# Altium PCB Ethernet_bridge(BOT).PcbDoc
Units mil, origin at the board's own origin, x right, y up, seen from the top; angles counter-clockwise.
Board outline 3110.24 x 1181.1 mil, 2 copper layers (Top Layer, Bottom Layer), stack 35.4 mil thick; 47 components, 34 nets, 155 pads, 0 vias.
Unrouted connection lines stored in the file: 106.
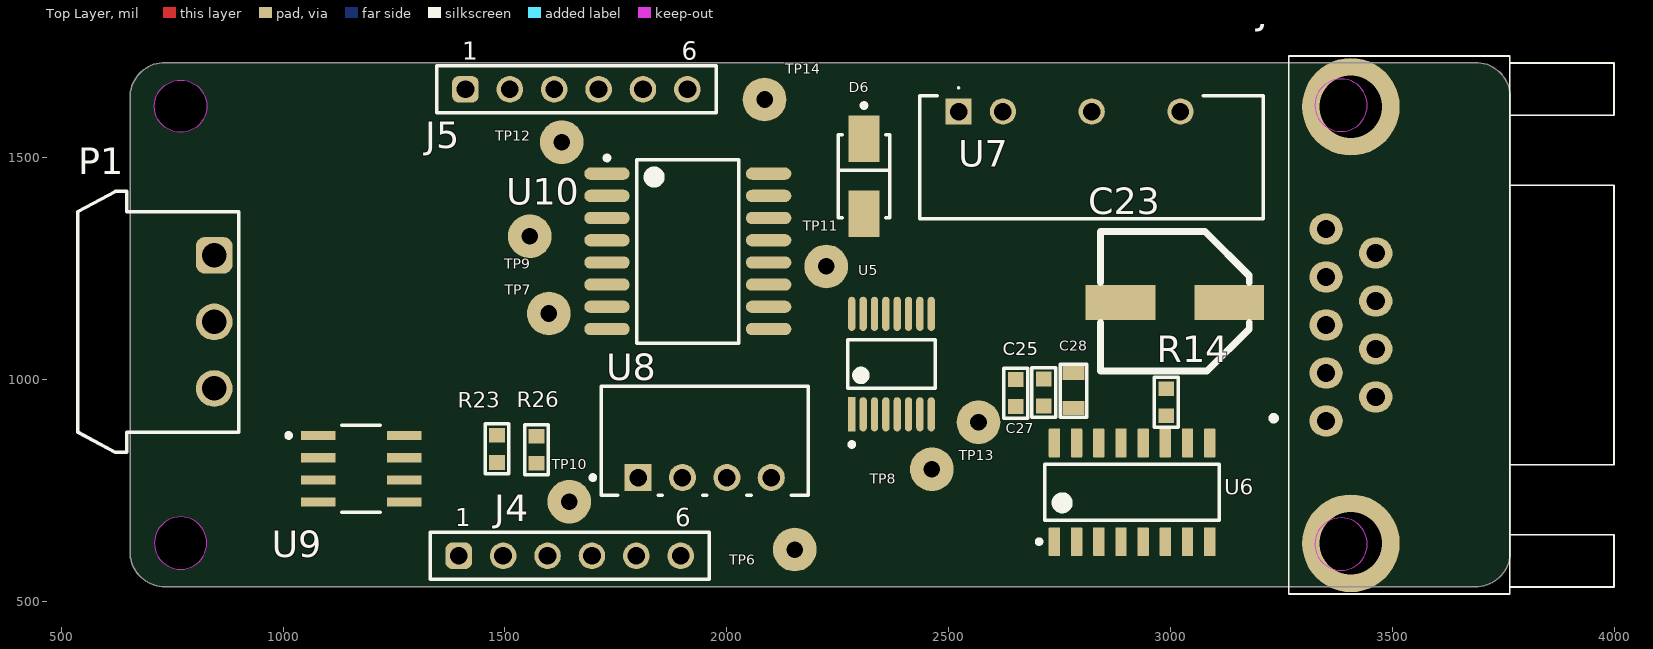
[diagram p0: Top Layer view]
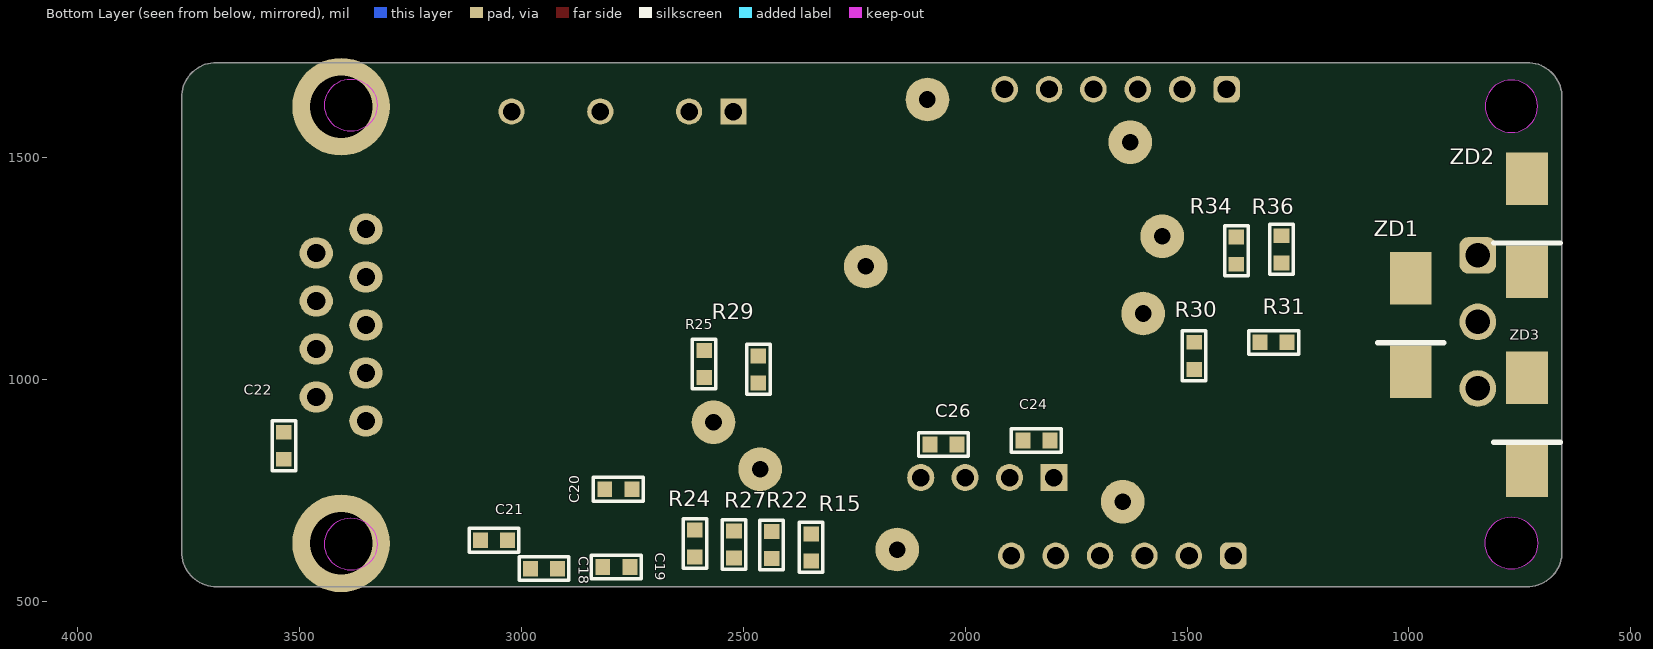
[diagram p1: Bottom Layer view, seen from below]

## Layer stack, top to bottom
Top Solder: solder mask 0.4, Solder Resist, Dk 3.5
Top Layer: signal copper 1.4
Dielectric 1: dielectric 32.6, FR-4, Dk 4.8
Bottom Layer: signal copper 1.4
Bottom Solder: solder mask 0.4, Solder Resist, Dk 3.5

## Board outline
733.99,532.25 cw(c733.99,610.99) 655.25,610.99 655.25,1634.61 cw(c733.99,1634.61) 733.99,1713.35 3686.75,1713.35 cw(c3686.75,1634.61) 3765.49,1634.61 3765.49,610.99 cw(c3686.75,610.99) 3686.75,532.25
cut-out: 3324.94,628.39 ccw(c3383.99,628.39) 3383.99,569.34 ccw(c3383.99,628.39) 3443.05,628.39 ccw(c3383.99,628.39) 3383.99,687.45 ccw(c3383.99,628.39)
cut-out: 3324.94,1617.21 ccw(c3383.99,1617.21) 3383.99,1558.16 ccw(c3383.99,1617.21) 3443.05,1617.21 ccw(c3383.99,1617.21) 3383.99,1676.27 ccw(c3383.99,1617.21)
cut-out: 769.42,1555.87 cw(c769.42,1614.93) 710.37,1614.93 cw(c769.42,1614.93) 769.42,1673.98 cw(c769.42,1614.93) 828.48,1614.93 cw(c769.42,1614.93)
cut-out: 710.37,630.68 ccw(c769.42,630.68) 769.42,571.62 ccw(c769.42,630.68) 828.48,630.68 ccw(c769.42,630.68) 769.42,689.73 ccw(c769.42,630.68)

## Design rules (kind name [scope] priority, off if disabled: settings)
Clearance [All] p1: gap=1 ignorepadtopadclearanceinfootprint=TRUE
ComponentClearance ComponentClearance_1 [All] p1: gap=-100 collisioncheckmode=3 verticalgap=100000 showdistances=FALSE
PolygonConnect [All] p1: connectstyle=Relief reliefconductorwidth=10 reliefentries=4 polygonreliefangle="90 Angle" airgapwidth=10
RoutingVias [All] p1: holewidth=28 width=50 viastyle="Through Hole" minholewidth=28 minwidth=50 maxholewidth=28 maxwidth=50
ShortCircuit [All] p1: allowed=TRUE
SolderMaskExpansion [All] p1: expansion=4 istentingtop=FALSE
SupplyNets "Schematic Supply Nets_6" [InNet('GND')] p1: voltage=0.000
SupplyNets "Schematic Supply Nets_5" [InNet('+5V')] p2: voltage=0.000
SupplyNets "Schematic Supply Nets_4" [InNet('VCC')] p3: voltage=0.000
SupplyNets "Schematic Supply Nets_3" [InNet('GND_2')] p4: voltage=0.000
SupplyNets "Schematic Supply Nets_2" [InNet('+3V3_MCU')] p5: voltage=0.000
SupplyNets "Schematic Supply Nets" [InNet('+5V_ISO')] p6: voltage=0.000
Width [All] p1: maxlimit=10 minlimit=10 preferedwidth=10
28 further rules are at their usual default settings.

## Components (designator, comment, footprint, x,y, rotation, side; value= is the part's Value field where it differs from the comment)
C18 "0.1uF" CAP-0603 2949,573 r180 bottom
C19 "0.1uF" CAP-0603 2786,577 r180 bottom
C20 "0.1uF" CAP-0603 2781.49,752 r0 bottom
C21 "0.1uF" CAP-0603 3061.51,637 r180 bottom
C22 "100nF" CAP-0603 3535,850 r90 bottom
C23 "330uF 25V" CAP_SMD_Size_E 3007,1173 r0 top
C24 "100nF" CAP-0603 1839.49,862 r0 bottom
C25 "100nF" CAP-0603 2651,968.51 r90 top
C26 "100nF" CAP-0603 2049,853 r0 bottom
C27 "100nF" CAP-0603 2714,970 r90 top
C28 "0.47uF" CAP-0805 2781,974 r90 top
D6 "SS14" DO-214-AC 2309,1457 r90 top
J1 "DB9 pcb" DB-9_2 2365.19,1476.98 r90 top
J4 "61300611821" 61300611821 1646,602 r0 top
J5 "61300611821" 61300611821 1661,1653 r0 top
P1 "691305340003" 691305340003 719,1129 r270 top
R14 "33R" RES-0603 2990,948 r90 top
R15 "33R" RES-0603 2347,621 r90 bottom
R22 "10K" RES-0603 2436,626.51 r90 bottom
R23 "10K" RES-0603 1482,843 r90 top
R24 "10K" RES-0603 2609,629.51 r90 bottom
R25 "10K" RES-0603 2588,1034 r90 bottom
R26 "10K" RES-0603 1571,841 r90 top
R27 "100" RES-0603 2521,627.51 r90 bottom
R29 "100" RES-0603 2466,1022 r90 bottom
R30 "10K" RES-0603 1484,1052.51 r90 bottom
R31 "10K" RES-0603 1305,1083 r180 bottom
R34 "10K" RES-0603 1389,1289.51 r90 bottom
R36 "10K" RES-0603 1287,1292.51 r90 bottom
TP6 "Test_Point_PCB" Test_Point 2153,616 r0 top
TP7 "Test_Point_PCB" Test_Point 1599,1148 r0 top
TP8 "Test_Point_PCB" Test_Point 2462,797 r0 top
TP9 "Test_Point_PCB" Test_Point 1556,1322 r0 top
TP10 "Test_Point_PCB" Test_Point 1645,724 r90 top
TP11 "Test_Point_PCB" Test_Point 2224,1254 r90 top
TP12 "Test_Point_PCB" Test_Point 1628,1534 r90 top
TP13 "" Test_Point 2567,903 r90 top
TP14 "Test_Point_PCB" Test_Point 2085,1630 r90 top
U5 "TMUX1574PWR" TSSOP-16-A 2371,1034 r90 top
U6 "MAX3232" SOIC-16-M 2913,745 r90 top
U7 "B1212S-3WR2" B1212S-3WR2 2822,1508 r0 top
U8 "B0505S-1W" B0505S-1W 1950,861 r0 top
U9 "MAX485" SOIC-8-MFG 1176,798 r0 top
U10 "ADUM1401BRWZ" ADI-RW-16_M 1912,1288 r0 top
ZD1 "P6SMB16CA" DO-214AA 996,1032 r90 bottom
ZD2 "P6SMB16CA" DO-214AA 734,1257 r90 bottom
ZD3 "P6SMB16CA" DO-214AA 734,808 r90 bottom

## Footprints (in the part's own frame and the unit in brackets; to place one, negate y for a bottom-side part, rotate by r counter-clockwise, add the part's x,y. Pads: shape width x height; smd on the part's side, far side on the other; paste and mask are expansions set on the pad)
61300611821 [mm] "Socket Header, Pitch 2.54 mm, THT, Vertical, single row, 6p"
  rrect50% 1.52x1.52 hole 1.02: 1(-6.35,0)
  round 1.52 hole 1.02: 2(-3.81,0) 3(-1.27,0) 4(1.27,0) 5(3.81,0) 6(6.35,0)
  silkscreen extent -8,-1.35 8,1.35, body extent -7.87,-1.25 7.87,1.25, height 8.55
691305340003 [mm] "Horizontal PCB Header with Plastic Latch, pitch 3.81mm, 03p"
  rrect50% 2.1x2.1 hole 1.4: 1(-3.81,3.2)
  round 2.1 hole 1.4: 2(0,3.2) 3(3.81,3.2)
  silkscreen extent -7.47,-4.6 7.47,4.6, body extent -7.46,-4.6 7.46,4.6, height 7.25
ADI-RW-16_M [mm] "SOIC, 16-Leads, Body 10.3x7.5mm, Pitch 1.27mm, IPC Low Density"
  oval 2.6x0.7 smd: 1(-4.625,4.445) 2(-4.625,3.175) 3(-4.625,1.905) 4(-4.625,0.635) 5(-4.625,-0.635) 6(-4.625,-1.905) 7(-4.625,-3.175) 8(-4.625,-4.445) 9(4.625,-4.445) 10(4.625,-3.175) 11(4.625,-1.905) 12(4.625,-0.635) 13(4.625,0.635) 14(4.625,1.905) 15(4.625,3.175) 16(4.625,4.445)
  silkscreen extent -4.75,-5.25 2.93,5.47, body extent -3.8,-5.25 3.8,5.25, height 2.65
B0505S-1W [mm]
  rect 1.55x1.55 hole 1 paste-2539.97 mask+0: 1(-3.81,-2.1)
  round 1.55 hole 1 paste-2539.97 mask+0: 2(-1.27,-2.1) 3(1.27,-2.1) 4(3.81,-2.1)
  silkscreen extent -6.52,-3.13 5.92,3.13, body extent -6.02,-3.22 6.02,3.22, height 0.25
B1212S-3WR2 [mm]
  rect 1.5x1.5 hole 1: 1(-7.62,2.413)
  round 1.5 hole 1: 2(-5.08,2.413) 4(0,2.413) 6(5.08,2.413)
  silkscreen extent -9.83,-3.74 9.82,3.81, body extent -9.8,-3.68 9.8,3.32, height 10
CAP-0603 [mm]
  rect 0.85x0.9 smd: 1(-0.775,0) 2(0.775,0)
  silkscreen extent -1.43,-0.67 1.43,0.67, body extent -0.8,-0.4 0.8,0.4, height 0.8
CAP-0805 [mm]
  rect 0.8x1.25 smd mask+0.015: 1(-1,0) 2(1,0)
  silkscreen extent -1.52,-0.76 1.52,0.76, body extent -1,-0.62 1,0.63, height 0.8
CAP_SMD_Size_E [mm]
  rect 4x2 smd: 1(3.175,0) 2(-3.048,0)
  silkscreen extent -4.19,-3.94 4.32,4.06, body extent -4.25,-4 4.25,4, height 10.59
DB-9_2 [mil]
  oval 70x75 hole 40.94: 1(-570.98,-985) 2(-462.99,-985) 3(-355,-985) 4(-246.97,-985) 5(-138.98,-985) 6(-516.97,-1096.81) 7(-408.98,-1096.81) 8(-300.98,-1096.81) 9(-192.99,-1096.81)
  round 220 hole 140.87: MH1(-846.93,-1040.91) MH2(136.93,-1040.91)
  silkscreen extent -961,-1634 251,-861, body extent -971,-1655 261,-915, height 494
DO-214-AC [mm]
  rect 2.65x1.75 smd paste+0 mask+0: 1(-2.15,0) 2(2.15,0)
  silkscreen extent -2.37,-1.48 4.17,1.48, body extent -3.57,-1.58 3.57,1.58, height 0.25
DO-214AA [mm]
  rect 3x2.4 smd: 1(-0.381,0) 2(4.953,0)
  silkscreen extent 1.27,-1.91 1.27,1.91, body extent -0.53,-1.85 5.07,2.1, height 2.65
RES-0603 [mm]
  rect 0.85x0.9 smd: 1(-0.775,0) 2(0.775,0)
  silkscreen extent -1.43,-0.67 1.43,0.67, body extent -0.85,-0.45 0.85,0.45, height 0.55
SOIC-8-MFG [mm]
  rect 1.98x0.53 smd paste+0 mask+0: 1(-2.465,1.905) 2(-2.465,0.635) 3(-2.465,-0.635) 4(-2.465,-1.905) 5(2.465,-1.905) 6(2.465,-0.635) 7(2.465,0.635) 8(2.465,1.905)
  silkscreen extent -4.27,-2.5 1.1,2.5, body extent -3.55,-2.75 3.55,2.75, height 0.25
SOIC-16-M [mm]
  rrect15% 1.65x0.65 smd: 1(-2.825,4.445) 2(-2.825,3.175) 3(-2.825,1.905) 4(-2.825,0.635) 5(-2.825,-0.635) 6(-2.825,-1.905) 7(-2.825,-3.175) 8(-2.825,-4.445) 9(2.825,-4.445) 10(2.825,-3.175) 11(2.825,-1.905) 12(2.825,-0.635) 13(2.825,0.635) 14(2.825,1.905) 15(2.825,3.175) 16(2.825,4.445)
  silkscreen extent -2.95,-5 1.6,5.44, body extent -3,-4.95 3,4.95, height 1.59
Test_Point [mm]
  round 2.5 hole 0.95: 1(0,0)
TSSOP-16-A [mm] "TSSOP-16 pacadge"
  rect 1.955x0.421 smd paste+0 mask+0: 1(-2.875,2.275)
  rrect100% 1.955x0.421 smd paste+0 mask+0: 2(-2.875,1.625) 3(-2.875,0.975) 4(-2.875,0.325) 5(-2.875,-0.325) 6(-2.875,-0.975) 7(-2.875,-1.625) 8(-2.875,-2.275) 9(2.875,-2.275) 10(2.875,-1.625) 11(2.875,-0.975) 12(2.875,-0.325) 13(2.875,0.325) 14(2.875,0.975) 15(2.875,1.625) 16(2.875,2.275)
  silkscreen extent -4.73,-2.5 1.4,2.5, body extent -4.35,-3 4.35,3, height 0.25

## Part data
C18 C19 C20 C21 C22 C24 C25 C26 C27 C28: library part CAP-NON-POLAR
C23: library part CAP_POL_SMD
J1: library part DB9
J4 J5: "WR-PHD Socket Header, THT, Vertical, pitch 2.54mm, 1 Row, 6P", Contact Resistance=20mΩ, Manufacturer="Wurth Elektronik", Operating Temperature Max=125°C, Operating Temperature Min=-40°C, Rated Current=3A, Withstanding Voltage=500V, Working Voltage=250V
P1: "WR-TBL Series 3053 Horizontal PCB Header, THT, pitch 3.81mm, 3p", Manufacturer="Wurth Elektronik", Operating Temperature Max=105°C, Operating Temperature Min=-40°C, Rated Current=12A, Working Voltage=300V
R14 R15 R22 R23 R24 R25 R26 R27 R29 R30 R31 R34 R36: library part RES-CONST
TP6 TP7 TP8 TP9 TP10 TP11 TP12 TP13 TP14: library part TP_PCB?, "Test_Point"
U10: library part CMP-0534-00565-1, "Quad Channel Digital Isolator, 2.5 KV rms Insulation Rating, 10 Mbps Data Rate, 50 ns Delay, Industrial, 16-pin SOIC (RW-16), Tube", Manufacturer="Analog Devices", Max Operating Temp (degreesC)=125

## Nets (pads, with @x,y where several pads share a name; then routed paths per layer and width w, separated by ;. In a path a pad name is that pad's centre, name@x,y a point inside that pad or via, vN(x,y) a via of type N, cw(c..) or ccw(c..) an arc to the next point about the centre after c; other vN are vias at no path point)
+3V3_MCU: J4.4 J5.1 R23.2 R26.2 U10.1 U10.7
+5V: C24.2 J4.3 U8.2
+5V_ISO: C25.2 C26.2 C27.2 C28.1 R22.2 R24.2 R25.2 TP6.1 U5.16 U6.16 U8.4 U9.8 U10.10 U10.16
GND: C24.1 J4.5 J4.6 J5.6 R30.1 R31.1 U7.4 U8.1 U10.2 U10.8
GND_2: C20.1 C21.1 C22.1 C23.2 C25.1 C26.1 C27.1 C28.2 J1.5 J1.MH1 J1.MH2 P1.2 R34.1 R36.1 TP14.1 U5.8 U5.15 U6.15 U7.2 U8.3 U9.5 U10.9 U10.15 ZD2.1 ZD3.1
NetC18_1: C18.1 U6.5
NetC18_2: C18.2 U6.4
NetC19_1: C19.1 U6.3
NetC19_2: C19.2 U6.1
NetC20_2: C20.2 U6.2
NetC21_2: C21.2 U6.6
NetC22_2: C22.2 C23.1 J1.9 U7.1
NetD6_1: D6.1 U7.6
NetJ1_2: J1.2 U6.13
NetJ1_3: J1.3 U6.14
NetJ5_2: J5.2 R31.2 TP9.1 U10.3
NetJ5_3: J5.3 R26.1 TP10.1 U10.4
NetJ5_4: J5.4 R23.1 TP12.1 U10.6
NetJ5_5: J5.5 R30.2 TP7.1 U10.5
NetP1_1: P1.1 R22.1 U9.6 ZD1.2 ZD2.2
NetP1_3: P1.3 R34.2 U9.7 ZD1.1 ZD3.2
NetR14_1: R14.1 U6.11
NetR14_2: R14.2 U5.2
NetR15_1: R15.1 U6.12
NetR15_2: R15.2 U5.5
NetR24_1: R24.1 R27.1 TP8.1 U9.4
NetR25_1: R25.1 R29.1 TP13.1 U9.1
NetR27_2: R27.2 U5.3
NetR29_2: R29.2 U5.6
NetR36_2: R36.2 TP11.1 U9.2 U9.3 U10.12
NetU5_1: U5.1 U10.14
NetU5_4: U5.4 U10.13
NetU5_7: U5.7 U10.11
VCC: D6.2 J4.1 J4.2
pads on no net: J1.1 J1.4 J1.6 J1.7 J1.8 U5.9 U5.10 U5.11 U5.12 U5.13 U5.14 U6.7 U6.8 U6.9 U6.10

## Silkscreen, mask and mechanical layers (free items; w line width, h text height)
Mechanical 1:
  circle w0.5: c769.42,1614.93 r59.06
  circle w0.5: c769.42,630.68 r59.06
  circle w0.5: c3383.99,628.39 r59.06
  circle w0.5: c3383.99,1617.21 r59.06
  lines w0.5: 655.25,610.99 ccw(c733.99,610.99) 733.99,532.25 3686.75,532.25 ccw(c3686.75,610.99) 3765.49,610.99 3765.49,1634.61 ccw(c3686.75,1634.61) 3686.75,1713.35 733.99,1713.35 ccw(c733.99,1634.61) 655.25,1634.61 655.25,610.99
